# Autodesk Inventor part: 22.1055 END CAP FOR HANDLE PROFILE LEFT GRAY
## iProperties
Created: 2007-01
Part Number: 22.1055 END CAP FOR HANDLE PROFILE LEFT GRAY
Document SubType Name: Modeling
Designer: Andy Moles
Density: 1 g/cm^3
Mass: 3.97417 g
Surface Area: 32.835 cm^2
Volume: 3.97417 cm^3
Author: Andy Moles
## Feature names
1. Base1
